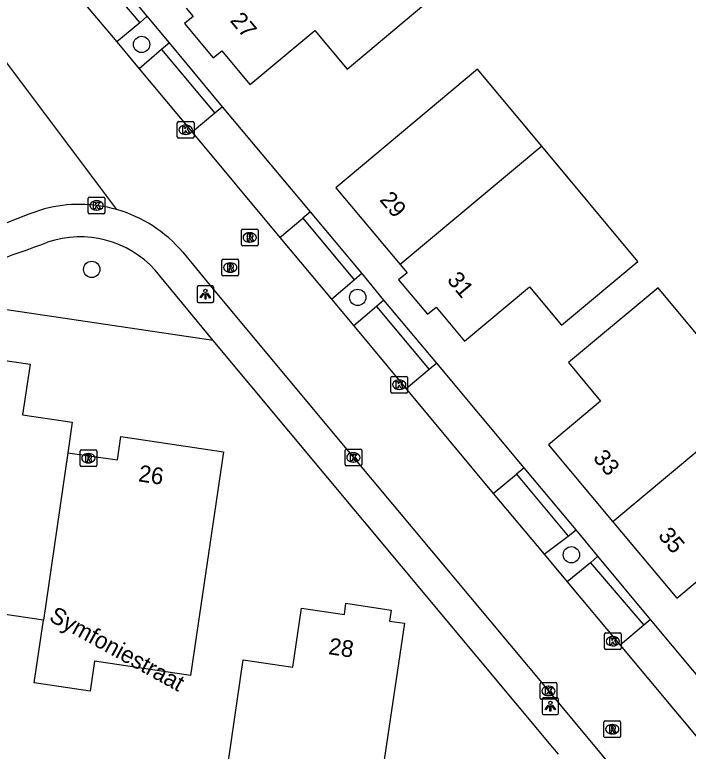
# Model space of a CAD drawing. Extents: x 164150 to 165261, y 382513 to 383432.
# Drawn here: x 164761.73 to 164802.1, y 383009.76 to 383053.88 of the extents above; entities that cross this region are included whole.
import ezdxf

# ---------------------------------------------------------------- set-up
doc = ezdxf.new("R2010")
doc.units = 0
for name, color, linetype in [('IMGEO_Boom', 7, 'Continuous'), ('IMGEO_Groenvoorziening', 7, 'Continuous'), ('IMGEO_Kolk', 7, 'Continuous'), ('IMGEO_Lichtpunt', 7, 'Continuous'), ('IMGEO_Openbare_ruimte_label', 7, 'Continuous'), ('IMGEO_Pand', 7, 'Continuous'), ('IMGEO_Pand_nummerreeks', 7, 'Continuous'), ('IMGEO_Parkeervlak_open', 7, 'Continuous'), ('IMGEO_Rijbaan_lokaal_open', 7, 'Continuous'), ('IMGEO_Rioolput', 7, 'Continuous'), ('IMGEO_Voetpad_open', 7, 'Continuous')]:
    doc.layers.add(name, color=color, linetype=linetype)

msp = doc.modelspace()

# ---------------------------------------------------------------- linework, layer by layer
at = {"layer": 'IMGEO_Boom'}
for centre in [(164769.334, 383052.103), (164766.345, 383038.63), (164782.284, 383036.954), (164795.095, 383021.53)]:
    msp.add_circle(centre, 0.489, dxfattribs=at)
at = {"layer": 'IMGEO_Groenvoorziening'}
for points in [[(164771.005, 383052.196), (164769.673, 383053.79)], [(164783.857, 383036.783), (164782.539, 383038.402)], [(164773.625, 383034.37), (164756.914, 383036.848), (164756.945, 383037.007)], [(164796.68, 383021.442), (164795.373, 383023.024)]]:
    msp.add_lwpolyline(points, dxfattribs=at)
at = {"layer": 'IMGEO_Kolk'}
for p, q in [((164771.474, 383046.566), (164771.474, 383047.418)), ((164771.549, 383047.492), (164772.401, 383047.492)), ((164771.962, 383047.272), (164771.987, 383047.272)), ((164772.475, 383047.418), (164772.475, 383046.566)), ((164771.985, 383046.712), (164771.96, 383046.712)), ((164772.401, 383046.492), (164771.549, 383046.492)), ((164766.133, 383042.035), (164766.133, 383042.887)), ((164766.208, 383042.961), (164767.06, 383042.961)), ((164766.621, 383042.741), (164766.646, 383042.741)), ((164767.134, 383042.887), (164767.134, 383042.035)), ((164767.06, 383041.961), (164766.208, 383041.961)), ((164766.644, 383042.181), (164766.619, 383042.181)), ((164784.275, 383031.295), (164784.275, 383032.147)), ((164784.35, 383032.221), (164785.202, 383032.221)), ((164785.276, 383032.147), (164785.276, 383031.295)), ((164784.763, 383032.001), (164784.788, 383032.001)), ((164784.786, 383031.441), (164784.761, 383031.441)), ((164785.202, 383031.221), (164784.35, 383031.221)), ((164781.528, 383026.94), (164781.528, 383027.792)), ((164781.603, 383027.866), (164782.455, 383027.866)), ((164782.529, 383027.792), (164782.529, 383026.94)), ((164782.016, 383027.646), (164782.041, 383027.646)), ((164782.455, 383026.866), (164781.603, 383026.866)), ((164782.039, 383027.086), (164782.014, 383027.086)), ((164797.075, 383015.93), (164797.075, 383016.782)), ((164797.15, 383016.856), (164798.002, 383016.856)), ((164798.076, 383016.782), (164798.076, 383015.93)), ((164797.563, 383016.636), (164797.588, 383016.636)), ((164798.002, 383015.856), (164797.15, 383015.856)), ((164797.586, 383016.076), (164797.561, 383016.076)), ((164793.22, 383012.946), (164793.22, 383013.798)), ((164793.295, 383013.872), (164794.147, 383013.872)), ((164793.708, 383013.652), (164793.733, 383013.652)), ((164794.221, 383013.798), (164794.221, 383012.946)), ((164794.147, 383012.872), (164793.295, 383012.872)), ((164793.731, 383013.092), (164793.706, 383013.092))]:
    msp.add_line(p, q, dxfattribs=at)
for points in [[(164771.474, 383046.566), (164771.474, 383047.418)], [(164771.549, 383047.492), (164772.401, 383047.492)], [(164771.795, 383047.192), (164771.918, 383047.192), (164771.918, 383047.041), (164772.048, 383047.192), (164772.212, 383047.192), (164772.066, 383047.041), (164772.219, 383046.792), (164772.067, 383046.792), (164771.982, 383046.956), (164771.918, 383046.889), (164771.918, 383046.792), (164771.795, 383046.792), (164771.795, 383047.192)], [(164772.475, 383047.418), (164772.475, 383046.566)], [(164772.401, 383046.492), (164771.549, 383046.492)], [(164766.133, 383042.035), (164766.133, 383042.887)], [(164766.208, 383042.961), (164767.06, 383042.961)], [(164767.134, 383042.887), (164767.134, 383042.035)], [(164766.454, 383042.661), (164766.577, 383042.661), (164766.577, 383042.51), (164766.707, 383042.661), (164766.871, 383042.661), (164766.725, 383042.51), (164766.878, 383042.261), (164766.726, 383042.261), (164766.641, 383042.425), (164766.577, 383042.358), (164766.577, 383042.261), (164766.454, 383042.261), (164766.454, 383042.661)], [(164767.06, 383041.961), (164766.208, 383041.961)], [(164784.275, 383031.295), (164784.275, 383032.147)], [(164784.35, 383032.221), (164785.202, 383032.221)], [(164785.276, 383032.147), (164785.276, 383031.295)], [(164784.596, 383031.921), (164784.719, 383031.921), (164784.719, 383031.77), (164784.849, 383031.921), (164785.013, 383031.921), (164784.867, 383031.77), (164785.02, 383031.521), (164784.868, 383031.521), (164784.783, 383031.685), (164784.719, 383031.618), (164784.719, 383031.521), (164784.596, 383031.521), (164784.596, 383031.921)], [(164785.202, 383031.221), (164784.35, 383031.221)], [(164781.528, 383026.94), (164781.528, 383027.792)], [(164781.603, 383027.866), (164782.455, 383027.866)], [(164782.529, 383027.792), (164782.529, 383026.94)], [(164781.849, 383027.566), (164781.972, 383027.566), (164781.972, 383027.415), (164782.102, 383027.566), (164782.266, 383027.566), (164782.12, 383027.415), (164782.273, 383027.166), (164782.121, 383027.166), (164782.036, 383027.33), (164781.972, 383027.263), (164781.972, 383027.166), (164781.849, 383027.166), (164781.849, 383027.566)], [(164782.455, 383026.866), (164781.603, 383026.866)], [(164797.075, 383015.93), (164797.075, 383016.782)], [(164797.15, 383016.856), (164798.002, 383016.856)], [(164798.076, 383016.782), (164798.076, 383015.93)], [(164797.396, 383016.556), (164797.519, 383016.556), (164797.519, 383016.405), (164797.649, 383016.556), (164797.813, 383016.556), (164797.667, 383016.405), (164797.82, 383016.156), (164797.668, 383016.156), (164797.583, 383016.32), (164797.519, 383016.253), (164797.519, 383016.156), (164797.396, 383016.156), (164797.396, 383016.556)], [(164798.002, 383015.856), (164797.15, 383015.856)], [(164793.22, 383012.946), (164793.22, 383013.798)], [(164793.295, 383013.872), (164794.147, 383013.872)], [(164794.221, 383013.798), (164794.221, 383012.946)], [(164793.541, 383013.572), (164793.664, 383013.572), (164793.664, 383013.421), (164793.794, 383013.572), (164793.958, 383013.572), (164793.812, 383013.421), (164793.965, 383013.172), (164793.813, 383013.172), (164793.728, 383013.336), (164793.664, 383013.269), (164793.664, 383013.172), (164793.541, 383013.172), (164793.541, 383013.572)], [(164794.147, 383012.872), (164793.295, 383012.872)]]:
    msp.add_lwpolyline(points, dxfattribs=at)
for centre, start, end in [((164771.551, 383047.416), 91.552, 178.448), ((164771.551, 383047.416), 91.552, 178.448), ((164772.399, 383047.416), 1.552, 88.448), ((164772.399, 383047.416), 1.552, 88.448), ((164771.551, 383046.568), 181.552, 268.448), ((164771.551, 383046.568), 181.552, 268.448), ((164772.399, 383046.568), 271.552, 358.448), ((164772.399, 383046.568), 271.552, 358.448), ((164766.21, 383042.885), 91.552, 178.448), ((164766.21, 383042.885), 91.552, 178.448), ((164767.058, 383042.885), 1.552, 88.448), ((164767.058, 383042.885), 1.552, 88.448), ((164766.21, 383042.037), 181.552, 268.448), ((164766.21, 383042.037), 181.552, 268.448), ((164767.058, 383042.037), 271.552, 358.448), ((164767.058, 383042.037), 271.552, 358.448), ((164784.352, 383032.145), 91.552, 178.448), ((164784.352, 383032.145), 91.552, 178.448), ((164785.2, 383032.145), 1.552, 88.448), ((164785.2, 383032.145), 1.552, 88.448), ((164784.352, 383031.297), 181.552, 268.448), ((164784.352, 383031.297), 181.552, 268.448), ((164785.2, 383031.297), 271.552, 358.448), ((164785.2, 383031.297), 271.552, 358.448), ((164781.605, 383027.79), 91.552, 178.448), ((164781.605, 383027.79), 91.552, 178.448), ((164782.453, 383027.79), 1.552, 88.448), ((164782.453, 383027.79), 1.552, 88.448), ((164781.605, 383026.942), 181.552, 268.448), ((164781.605, 383026.942), 181.552, 268.448), ((164782.453, 383026.942), 271.552, 358.448), ((164782.453, 383026.942), 271.552, 358.448), ((164797.152, 383016.78), 91.552, 178.448), ((164797.152, 383016.78), 91.552, 178.448), ((164798, 383016.78), 1.552, 88.448), ((164798, 383016.78), 1.552, 88.448), ((164797.152, 383015.932), 181.552, 268.448), ((164797.152, 383015.932), 181.552, 268.448), ((164798, 383015.932), 271.552, 358.448), ((164798, 383015.932), 271.552, 358.448), ((164793.297, 383013.796), 91.552, 178.448), ((164793.297, 383013.796), 91.552, 178.448), ((164794.145, 383013.796), 1.552, 88.448), ((164794.145, 383013.796), 1.552, 88.448), ((164793.297, 383012.948), 181.552, 268.448), ((164793.297, 383012.948), 181.552, 268.448), ((164794.145, 383012.948), 271.552, 358.448), ((164794.145, 383012.948), 271.552, 358.448)]:
    msp.add_arc(centre, 0.0765, start, end, dxfattribs=at)
for centre, major_axis, ratio, start_param, end_param in [((164771.961, 383046.992), (-0.387, 0.002), 0.722429, 4.712389, 7.853982), ((164771.986, 383046.992), (-0.39, 0.002), 0.717154, 1.570796, 4.712389), ((164766.62, 383042.461), (-0.387, 0.002), 0.722429, 4.712389, 7.853982), ((164766.645, 383042.461), (-0.39, 0.002), 0.717154, 1.570796, 4.712389), ((164784.762, 383031.721), (-0.387, 0.002), 0.722429, 4.712389, 7.853982), ((164784.787, 383031.721), (-0.39, 0.002), 0.717154, 1.570796, 4.712389), ((164782.015, 383027.366), (-0.387, 0.002), 0.722429, 4.712389, 7.853982), ((164782.04, 383027.366), (-0.39, 0.002), 0.717154, 1.570796, 4.712389), ((164797.562, 383016.356), (-0.387, 0.002), 0.722429, 4.712389, 7.853982), ((164797.587, 383016.356), (-0.39, 0.002), 0.717154, 1.570796, 4.712389), ((164793.707, 383013.372), (-0.387, 0.002), 0.722429, 4.712389, 7.853982), ((164793.732, 383013.372), (-0.39, 0.002), 0.717154, 1.570796, 4.712389)]:
    msp.add_ellipse(centre, major_axis=major_axis, ratio=ratio, start_param=start_param, end_param=end_param, dxfattribs=at)
at = {"layer": 'IMGEO_Lichtpunt'}
for p, q in [((164772.659, 383037.541), (164772.659, 383036.734)), ((164772.659, 383037.541), (164772.659, 383036.734)), ((164773.561, 383037.636), (164772.753, 383037.636)), ((164773.561, 383037.636), (164772.753, 383037.636)), ((164773.655, 383036.734), (164773.655, 383037.541)), ((164773.655, 383036.734), (164773.655, 383037.541)), ((164772.753, 383036.64), (164773.561, 383036.64)), ((164772.753, 383036.64), (164773.561, 383036.64)), ((164793.333, 383012.861), (164793.333, 383012.054)), ((164793.333, 383012.861), (164793.333, 383012.054)), ((164794.235, 383012.956), (164793.427, 383012.956)), ((164794.235, 383012.956), (164793.427, 383012.956)), ((164794.329, 383012.054), (164794.329, 383012.861)), ((164794.329, 383012.054), (164794.329, 383012.861)), ((164793.427, 383011.96), (164794.235, 383011.96)), ((164793.427, 383011.96), (164794.235, 383011.96))]:
    msp.add_line(p, q, dxfattribs=at)
for points in [[(164773.033, 383037.205), (164773.072, 383037.177), (164772.884, 383036.915), (164772.846, 383036.942), (164773.033, 383037.205)], [(164773.135, 383037.157), (164773.182, 383037.157), (164773.182, 383036.835), (164773.135, 383036.835), (164773.135, 383037.157)], [(164773.245, 383037.177), (164773.283, 383037.204), (164773.47, 383036.942), (164773.431, 383036.914), (164773.245, 383037.177)], [(164793.707, 383012.525), (164793.746, 383012.497), (164793.558, 383012.235), (164793.52, 383012.262), (164793.707, 383012.525)], [(164793.809, 383012.477), (164793.856, 383012.477), (164793.856, 383012.155), (164793.809, 383012.155), (164793.809, 383012.477)], [(164793.919, 383012.497), (164793.957, 383012.524), (164794.144, 383012.262), (164794.105, 383012.234), (164793.919, 383012.497)]]:
    msp.add_lwpolyline(points, dxfattribs=at)
for centre in [(164773.158, 383037.339), (164793.832, 383012.659)]:
    msp.add_circle(centre, 0.0994, dxfattribs=at)
for centre, start, end in [((164772.753, 383037.541), 90, 180), ((164772.753, 383037.541), 90, 180), ((164773.561, 383037.541), 0, 90), ((164773.561, 383037.541), 0, 90), ((164772.753, 383036.734), 180, 270), ((164772.753, 383036.734), 180, 270), ((164773.561, 383036.734), 270, 0), ((164773.561, 383036.734), 270, 360), ((164793.427, 383012.861), 90, 180), ((164793.427, 383012.861), 90, 180), ((164794.235, 383012.861), 0, 90), ((164794.235, 383012.861), 0, 90), ((164793.427, 383012.054), 180, 270), ((164793.427, 383012.054), 180, 270), ((164794.235, 383012.054), 270, 0), ((164794.235, 383012.054), 270, 360)]:
    msp.add_arc(centre, 0.0946, start, end, dxfattribs=at)
at = {"layer": 'IMGEO_Pand'}
for points in [[(164772.009, 383054.277), (164772.419, 383053.785), (164771.905, 383053.356), (164773.628, 383051.296), (164774.139, 383051.722), (164775.823, 383049.702), (164775.871, 383049.742), (164779.717, 383052.949), (164781.652, 383050.629), (164786.258, 383054.47), (164780.486, 383061.369)], [(164793.317, 383046.003), (164789.459, 383050.622), (164780.979, 383043.523), (164784.834, 383038.917)], [(164784.834, 383038.917), (164785.241, 383038.431), (164784.735, 383038.008), (164786.465, 383035.941), (164786.979, 383036.371), (164788.685, 383034.332), (164792.575, 383037.588), (164794.507, 383035.279), (164799.079, 383039.106), (164793.317, 383046.003)], [(164793.317, 383046.003), (164784.834, 383038.917)], [(164806.077, 383030.603), (164800.287, 383037.53), (164794.917, 383033.045), (164796.845, 383030.735), (164793.713, 383028.12), (164797.58, 383023.505)], [(164763.455, 383017.62), (164760.052, 383018.118), (164760.487, 383021.077), (164754.735, 383021.923), (164756.488, 383033.841), (164762.657, 383032.956), (164762.202, 383029.922), (164765.166, 383029.471), (164764.912, 383027.637)], [(164806.077, 383030.603), (164797.58, 383023.505)], [(164797.58, 383023.505), (164801.419, 383018.924), (164805.309, 383022.184), (164807.266, 383019.849), (164811.852, 383023.693), (164806.077, 383030.603)], [(164764.912, 383027.637), (164767.886, 383027.211), (164768.092, 383028.613), (164774.238, 383027.703), (164772.256, 383014.304), (164766.51, 383015.154), (164766.246, 383013.368), (164762.899, 383013.863), (164763.455, 383017.62)], [(164764.912, 383027.637), (164763.455, 383017.62)], [(164784.293, 383018.222), (164784.196, 383017.562), (164785.081, 383017.432), (164783.318, 383005.501), (164774.198, 383006.849), (164775.415, 383015.23), (164778.393, 383014.789), (164778.918, 383018.342), (164781.485, 383017.963), (164781.583, 383018.623), (164784.293, 383018.222)]]:
    msp.add_lwpolyline(points, dxfattribs=at)
at = {"layer": 'IMGEO_Parkeervlak_open'}
for points in [[(164769.236, 383053.402), (164767.857, 383052.253)], [(164770.53, 383051.801), (164769.192, 383050.647)], [(164780.707, 383036.845), (164782.079, 383038)], [(164783.41, 383036.401), (164782.046, 383035.254)], [(164793.463, 383021.56), (164794.892, 383022.646)], [(164796.234, 383021.058), (164794.843, 383019.914)]]:
    msp.add_lwpolyline(points, dxfattribs=at)
at = {"layer": 'IMGEO_Rijbaan_lokaal_open'}
for points in [[(164764.743, 383055.943), (164767.857, 383052.253)], [(164760.445, 383052.045), (164767.829, 383042.216)], [(164767.857, 383052.253), (164769.192, 383050.647)], [(164769.192, 383050.647), (164772.36, 383046.857)], [(164772.36, 383046.857), (164777.624, 383040.546)], [(164763.51, 383042.252), (164762.583, 383041.927), (164760.568, 383041.168), (164758.078, 383040.379)], [(164777.624, 383040.546), (164780.707, 383036.845)], [(164771.8, 383039.66), (164773.622, 383037.443), (164782.029, 383027.366), (164793.721, 383013.372), (164807.417, 382996.914), (164810.146, 382993.692), (164812.326, 382991.078)], [(164780.707, 383036.845), (164782.046, 383035.254)], [(164782.046, 383035.254), (164785.193, 383031.48)], [(164785.193, 383031.48), (164790.41, 383025.204)], [(164790.41, 383025.204), (164793.463, 383021.56)], [(164793.463, 383021.56), (164794.843, 383019.914)], [(164794.843, 383019.914), (164798.018, 383016.107)], [(164798.018, 383016.107), (164803.165, 383009.943)]]:
    msp.add_lwpolyline(points, dxfattribs=at)
for centre, radius, start, end in [((164765.604, 383034.401), 8.125, 74.1087, 104.9362), ((164765.606, 383034.4), 8.126, 40.3397, 74.1242)]:
    msp.add_arc(centre, radius, start, end, dxfattribs=at)
at = {"layer": 'IMGEO_Rioolput'}
for p, q in [((164775.317, 383040.12), (164775.317, 383040.972)), ((164775.392, 383041.046), (164776.244, 383041.046)), ((164776.318, 383040.972), (164776.318, 383040.12)), ((164775.805, 383040.826), (164775.83, 383040.826)), ((164775.828, 383040.266), (164775.803, 383040.266)), ((164776.244, 383040.046), (164775.392, 383040.046)), ((164774.223, 383039.241), (164775.075, 383039.241)), ((164774.148, 383038.315), (164774.148, 383039.167)), ((164774.636, 383039.021), (164774.661, 383039.021)), ((164775.149, 383039.167), (164775.149, 383038.315)), ((164774.659, 383038.461), (164774.634, 383038.461)), ((164775.075, 383038.241), (164774.223, 383038.241)), ((164765.643, 383026.891), (164765.643, 383027.743)), ((164765.718, 383027.817), (164766.57, 383027.817)), ((164766.644, 383027.743), (164766.644, 383026.891)), ((164766.131, 383027.597), (164766.156, 383027.597)), ((164766.154, 383027.037), (164766.129, 383027.037)), ((164766.57, 383026.817), (164765.718, 383026.817)), ((164797.04, 383010.65), (164797.04, 383011.502)), ((164797.115, 383011.576), (164797.967, 383011.576)), ((164798.041, 383011.502), (164798.041, 383010.65)), ((164797.528, 383011.356), (164797.553, 383011.356)), ((164797.967, 383010.576), (164797.115, 383010.576)), ((164797.551, 383010.796), (164797.526, 383010.796))]:
    msp.add_line(p, q, dxfattribs=at)
for points in [[(164775.317, 383040.12), (164775.317, 383040.972)], [(164775.392, 383041.046), (164776.244, 383041.046)], [(164776.318, 383040.972), (164776.318, 383040.12)], [(164775.906, 383040.744), (164775.654, 383040.746), (164775.654, 383040.346)], [(164775.832, 383040.665), (164775.778, 383040.665), (164775.778, 383040.584)], [(164775.778, 383040.584), (164775.83, 383040.584)], [(164775.654, 383040.346), (164775.778, 383040.346), (164775.778, 383040.508), (164775.789, 383040.508)], [(164775.836, 383040.479), (164775.907, 383040.346), (164776.047, 383040.346), (164775.982, 383040.472)], [(164776.244, 383040.046), (164775.392, 383040.046)], [(164774.223, 383039.241), (164775.075, 383039.241)], [(164774.148, 383038.315), (164774.148, 383039.167)], [(164774.737, 383038.939), (164774.485, 383038.941), (164774.485, 383038.541)], [(164774.663, 383038.86), (164774.609, 383038.86), (164774.609, 383038.779)], [(164774.609, 383038.779), (164774.661, 383038.779)], [(164775.149, 383039.167), (164775.149, 383038.315)], [(164774.485, 383038.541), (164774.609, 383038.541), (164774.609, 383038.703), (164774.62, 383038.703)], [(164774.667, 383038.674), (164774.738, 383038.541), (164774.878, 383038.541), (164774.813, 383038.667)], [(164775.075, 383038.241), (164774.223, 383038.241)], [(164765.643, 383026.891), (164765.643, 383027.743)], [(164765.718, 383027.817), (164766.57, 383027.817)], [(164766.644, 383027.743), (164766.644, 383026.891)], [(164766.232, 383027.515), (164765.98, 383027.517), (164765.98, 383027.117)], [(164765.98, 383027.117), (164766.104, 383027.117), (164766.104, 383027.279), (164766.115, 383027.279)], [(164766.158, 383027.436), (164766.104, 383027.436), (164766.104, 383027.355)], [(164766.104, 383027.355), (164766.156, 383027.355)], [(164766.162, 383027.25), (164766.233, 383027.117), (164766.373, 383027.117), (164766.308, 383027.243)], [(164766.57, 383026.817), (164765.718, 383026.817)], [(164797.04, 383010.65), (164797.04, 383011.502)], [(164797.115, 383011.576), (164797.967, 383011.576)], [(164798.041, 383011.502), (164798.041, 383010.65)], [(164797.629, 383011.274), (164797.377, 383011.276), (164797.377, 383010.876)], [(164797.377, 383010.876), (164797.501, 383010.876), (164797.501, 383011.038), (164797.512, 383011.038)], [(164797.555, 383011.195), (164797.501, 383011.195), (164797.501, 383011.114)], [(164797.501, 383011.114), (164797.553, 383011.114)], [(164797.559, 383011.009), (164797.63, 383010.876), (164797.77, 383010.876), (164797.705, 383011.002)], [(164797.967, 383010.576), (164797.115, 383010.576)]]:
    msp.add_lwpolyline(points, dxfattribs=at)
for centre, radius, start, end in [((164775.394, 383040.97), 0.0765, 91.552, 178.448), ((164775.394, 383040.97), 0.0765, 91.552, 178.448), ((164776.242, 383040.97), 0.0765, 1.552, 88.448), ((164776.242, 383040.97), 0.0765, 1.552, 88.448), ((164775.814, 383040.773), 0.19, 274.7715, 282.9687), ((164775.838, 383040.569), 0.0964, 77.0061, 93.1865), ((164775.852, 383040.626), 0.0378, 276.6634, 79.6772), ((164775.905, 383040.634), 0.109, 350.3612, 89.416), ((164775.903, 383040.634), 0.112, 277.5842, 350.9817), ((164775.887, 383040.419), 0.108, 29.5134, 73.7905), ((164775.394, 383040.122), 0.0765, 181.552, 268.448), ((164775.394, 383040.122), 0.0765, 181.552, 268.448), ((164775.788, 383040.455), 0.0533, 26.0293, 88.6989), ((164776.242, 383040.122), 0.0765, 271.552, 358.448), ((164776.242, 383040.122), 0.0765, 271.552, 358.448), ((164774.225, 383039.165), 0.0765, 91.552, 178.448), ((164774.225, 383039.165), 0.0765, 91.552, 178.448), ((164775.073, 383039.165), 0.0765, 1.552, 88.448), ((164775.073, 383039.165), 0.0765, 1.552, 88.448), ((164774.645, 383038.968), 0.19, 274.7715, 282.9687), ((164774.669, 383038.764), 0.0964, 77.0061, 93.1865), ((164774.683, 383038.821), 0.0378, 276.6634, 79.6772), ((164774.736, 383038.829), 0.109, 350.3612, 89.416), ((164774.734, 383038.829), 0.112, 277.5842, 350.9817), ((164774.225, 383038.317), 0.0765, 181.552, 268.448), ((164774.225, 383038.317), 0.0765, 181.552, 268.448), ((164774.619, 383038.65), 0.0533, 26.0293, 88.6989), ((164774.718, 383038.614), 0.108, 29.5134, 73.7905), ((164775.073, 383038.317), 0.0765, 271.552, 358.448), ((164775.073, 383038.317), 0.0765, 271.552, 358.448), ((164765.72, 383027.741), 0.0765, 91.552, 178.448), ((164765.72, 383027.741), 0.0765, 91.552, 178.448), ((164766.568, 383027.741), 0.0765, 1.552, 88.448), ((164766.568, 383027.741), 0.0765, 1.552, 88.448), ((164766.114, 383027.226), 0.0533, 26.0293, 88.6989), ((164766.14, 383027.544), 0.19, 274.7715, 282.9687), ((164766.164, 383027.34), 0.0964, 77.0061, 93.1865), ((164766.178, 383027.397), 0.0378, 276.6634, 79.6772), ((164766.231, 383027.405), 0.109, 350.3612, 89.416), ((164766.229, 383027.405), 0.112, 277.5842, 350.9817), ((164766.213, 383027.19), 0.108, 29.5134, 73.7905), ((164765.72, 383026.893), 0.0765, 181.552, 268.448), ((164765.72, 383026.893), 0.0765, 181.552, 268.448), ((164766.568, 383026.893), 0.0765, 271.552, 358.448), ((164766.568, 383026.893), 0.0765, 271.552, 358.448), ((164797.117, 383011.5), 0.0765, 91.552, 178.448), ((164797.117, 383011.5), 0.0765, 91.552, 178.448), ((164797.965, 383011.5), 0.0765, 1.552, 88.448), ((164797.965, 383011.5), 0.0765, 1.552, 88.448), ((164797.511, 383010.985), 0.0533, 26.0293, 88.6989), ((164797.537, 383011.303), 0.19, 274.7715, 282.9687), ((164797.561, 383011.099), 0.0964, 77.0061, 93.1865), ((164797.575, 383011.156), 0.0378, 276.6634, 79.6772), ((164797.628, 383011.164), 0.109, 350.3612, 89.416), ((164797.626, 383011.164), 0.112, 277.5842, 350.9817), ((164797.61, 383010.949), 0.108, 29.5134, 73.7905), ((164797.117, 383010.652), 0.0765, 181.552, 268.448), ((164797.117, 383010.652), 0.0765, 181.552, 268.448), ((164797.965, 383010.652), 0.0765, 271.552, 358.448), ((164797.965, 383010.652), 0.0765, 271.552, 358.448)]:
    msp.add_arc(centre, radius, start, end, dxfattribs=at)
for centre, major_axis, ratio, start_param, end_param in [((164775.804, 383040.546), (-0.387, 0.002), 0.722429, 4.712389, 7.853982), ((164775.829, 383040.546), (-0.39, 0.002), 0.717154, 1.570796, 4.712389), ((164774.635, 383038.741), (-0.387, 0.002), 0.722429, 4.712389, 7.853982), ((164774.66, 383038.741), (-0.39, 0.002), 0.717154, 1.570796, 4.712389), ((164766.13, 383027.317), (-0.387, 0.002), 0.722429, 4.712389, 7.853982), ((164766.155, 383027.317), (-0.39, 0.002), 0.717154, 1.570796, 4.712389), ((164797.527, 383011.076), (-0.387, 0.002), 0.722429, 4.712389, 7.853982), ((164797.552, 383011.076), (-0.39, 0.002), 0.717154, 1.570796, 4.712389)]:
    msp.add_ellipse(centre, major_axis=major_axis, ratio=ratio, start_param=start_param, end_param=end_param, dxfattribs=at)
at = {"layer": 'IMGEO_Voetpad_open'}
for points in [[(164769.673, 383053.79), (164766.59, 383057.489)], [(164766.111, 383057.083), (164769.236, 383053.402)], [(164769.673, 383053.79), (164769.236, 383053.402)], [(164771.005, 383052.196), (164770.53, 383051.801)], [(164774.189, 383048.376), (164771.005, 383052.196)], [(164770.53, 383051.801), (164773.722, 383047.994)], [(164774.189, 383048.376), (164773.722, 383047.994)], [(164779.454, 383042.072), (164774.189, 383048.376)], [(164773.722, 383047.994), (164772.36, 383046.857)], [(164779.454, 383042.072), (164778.997, 383041.695)], [(164782.539, 383038.402), (164779.454, 383042.072)], [(164777.624, 383040.546), (164778.997, 383041.695)], [(164778.997, 383041.695), (164782.079, 383038)], [(164773.625, 383034.37), (164770.154, 383038.576)], [(164782.079, 383038), (164782.539, 383038.402)], [(164783.857, 383036.783), (164783.41, 383036.401)], [(164787.032, 383033.002), (164783.857, 383036.783)], [(164783.41, 383036.401), (164786.565, 383032.625)], [(164794.329, 383009.577), (164793.988, 383009.985), (164773.625, 383034.37)], [(164786.565, 383032.625), (164785.193, 383031.48)], [(164787.032, 383033.002), (164786.565, 383032.625)], [(164792.262, 383026.731), (164787.032, 383033.002)], [(164792.262, 383026.731), (164791.805, 383026.354)], [(164795.373, 383023.024), (164792.262, 383026.731)], [(164790.41, 383025.204), (164791.805, 383026.354)], [(164791.805, 383026.354), (164794.892, 383022.646)], [(164794.892, 383022.646), (164795.373, 383023.024)], [(164796.68, 383021.442), (164796.234, 383021.058)], [(164799.84, 383017.655), (164796.68, 383021.442)], [(164796.234, 383021.058), (164799.444, 383017.319)], [(164799.84, 383017.655), (164799.444, 383017.319)], [(164805.017, 383011.469), (164799.84, 383017.655)], [(164799.444, 383017.319), (164798.018, 383016.107)]]:
    msp.add_lwpolyline(points, dxfattribs=at)
for centre, radius, start, end in [((164765.647, 383034.515), 6.067, 42.0159, 108.7539), ((164731.985, 383124.094), 89.631, 286.24859, 290.71977)]:
    msp.add_arc(centre, radius, start, end, dxfattribs=at)

# ---------------------------------------------------------------- texts
at = {"layer": 'IMGEO_Openbare_ruimte_label'}
msp.add_text('Symfoniestraat', height=1, rotation=331.1792, dxfattribs=at).set_placement((164763.725, 383017.61))
at = {"layer": 'IMGEO_Pand_nummerreeks'}
for s, rotation, p in [('27', 309.8146, (164774.591, 383053.522)), ('29', 309.9292, (164783.556, 383042.782)), ('31', 309.9178, (164787.592, 383037.976)), ('33', 309.9636, (164796.343, 383027.318)), ('26', 351.5775, (164769.099, 383025.936)), ('35', 309.9636, (164800.246, 383022.661)), ('28', 351.6004, (164780.493, 383015.582))]:
    msp.add_text(s, height=1, rotation=rotation, dxfattribs=at).set_placement(p)

doc.saveas('drawing.dxf')
